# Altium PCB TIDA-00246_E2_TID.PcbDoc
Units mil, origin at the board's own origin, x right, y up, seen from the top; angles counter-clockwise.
Board outline 4000 x 2300 mil, 2 copper layers (Top Layer, Bottom Layer), stack 62 mil thick; 73 components, 44 nets, 230 pads, 54 vias.
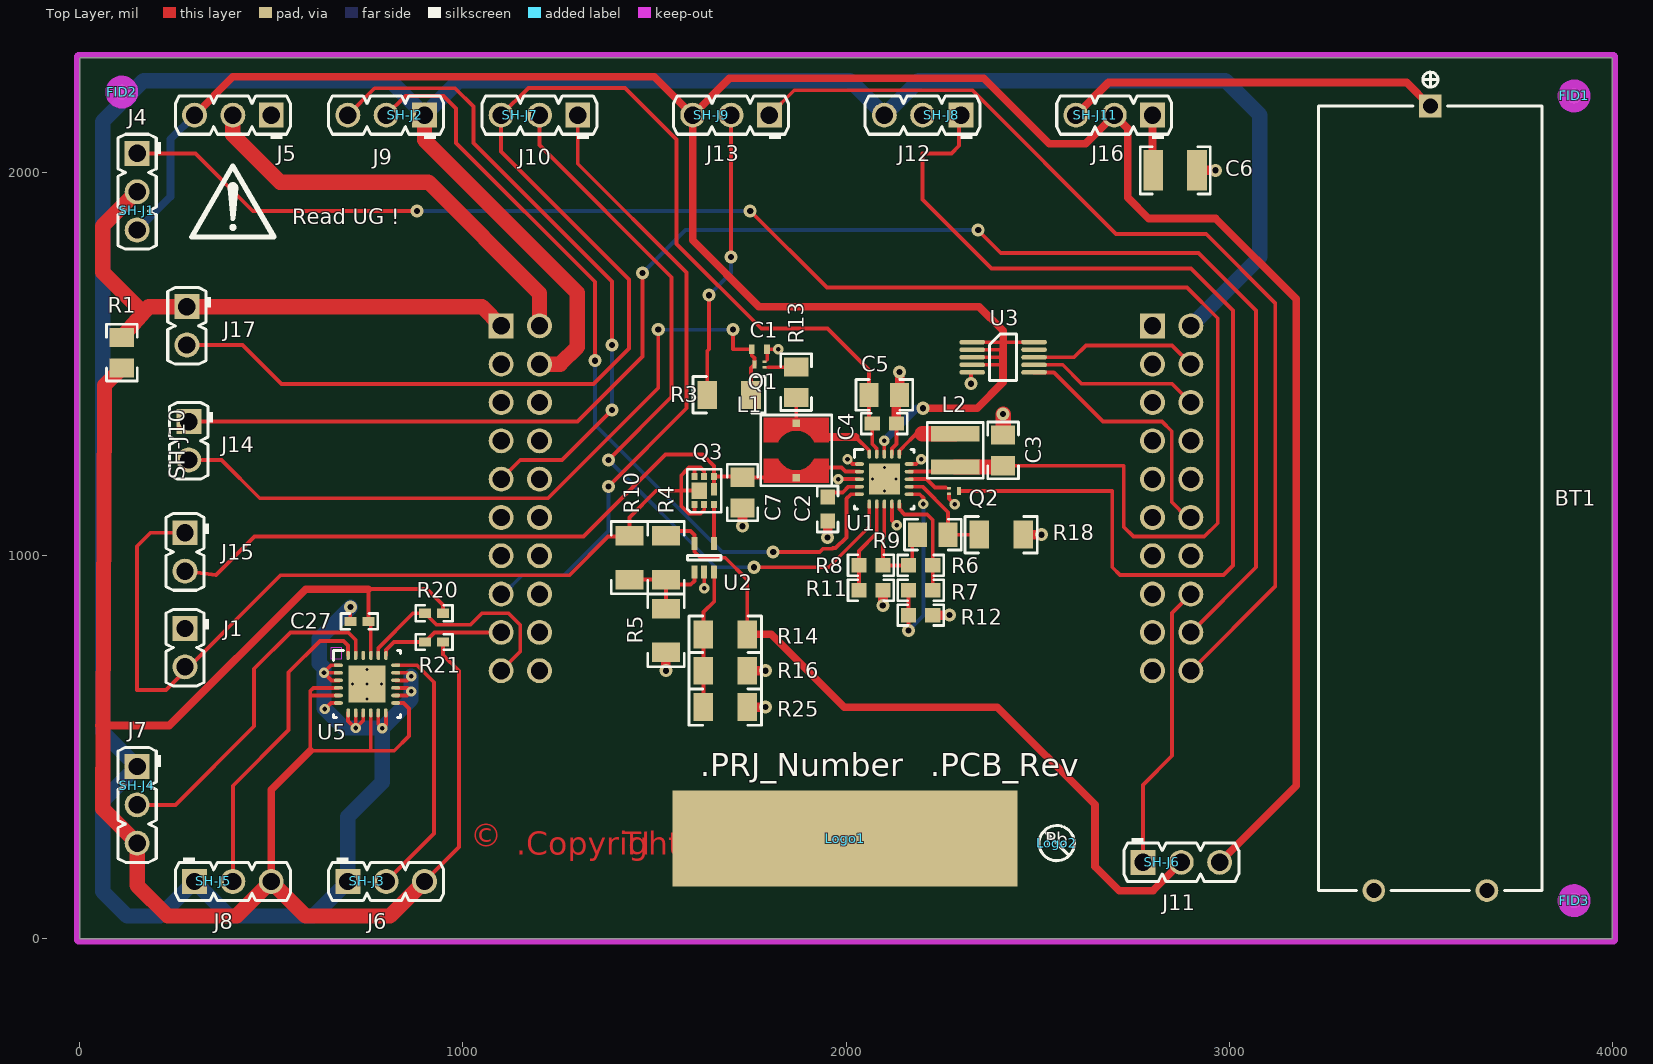
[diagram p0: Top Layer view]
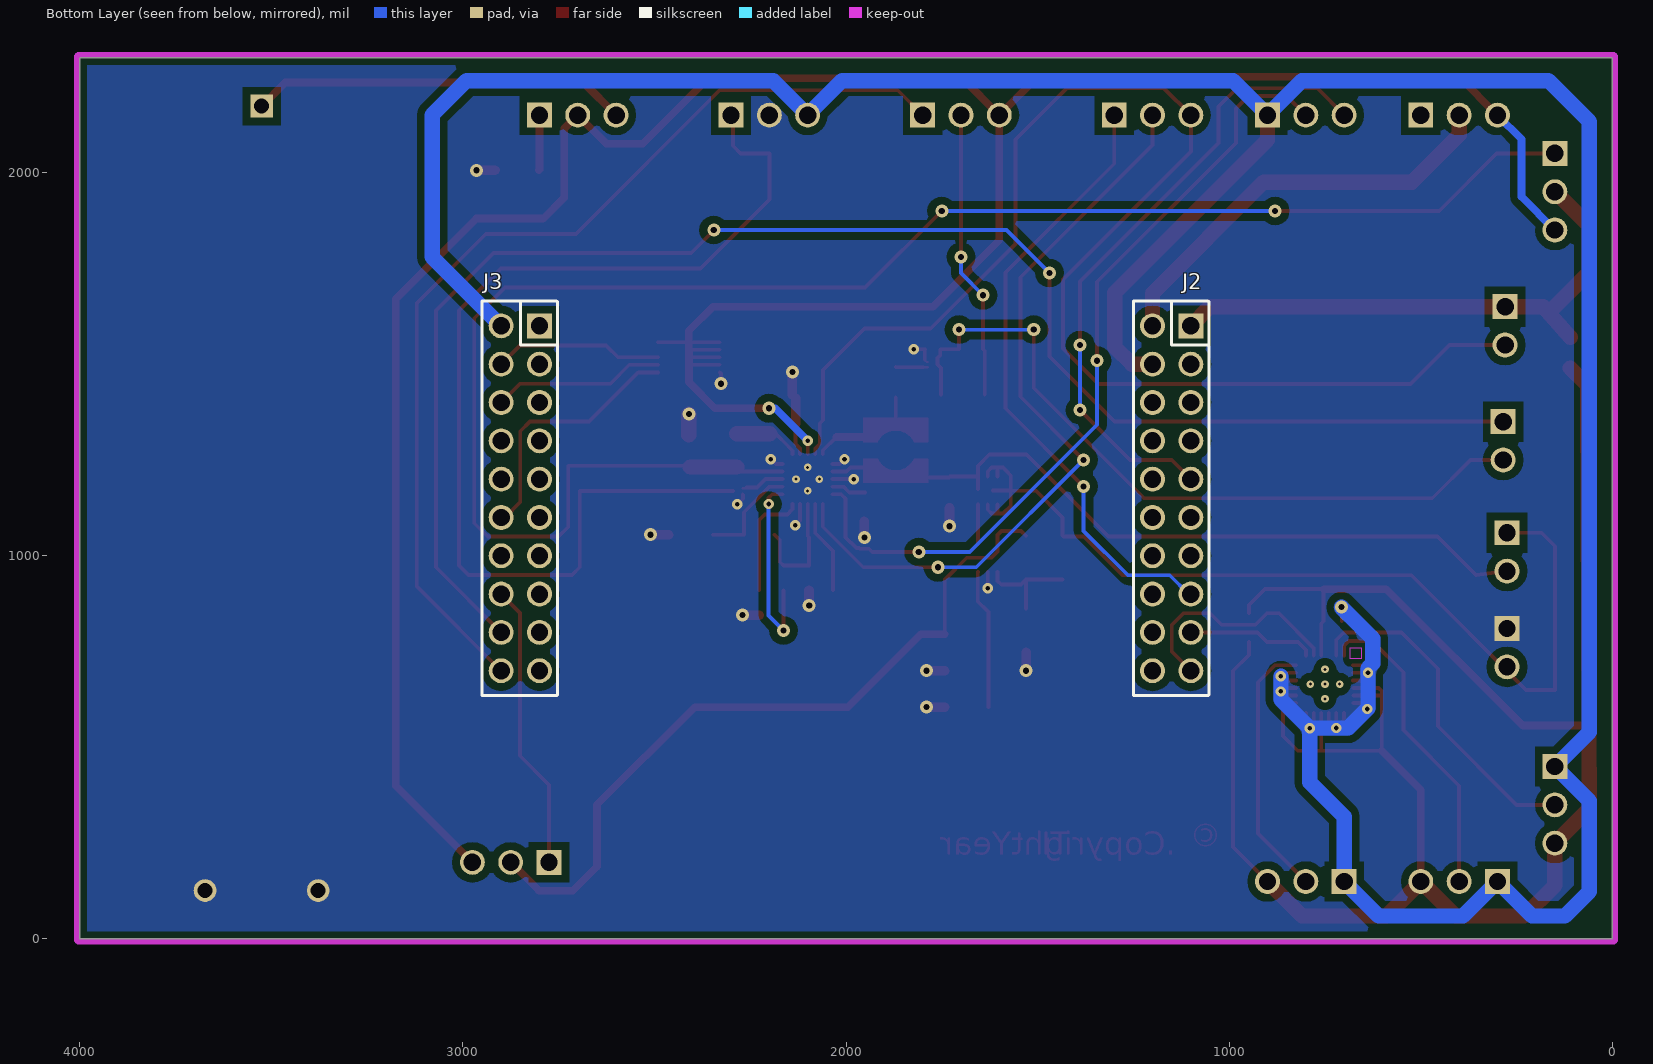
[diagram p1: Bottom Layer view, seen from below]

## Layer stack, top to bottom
Top Solder: solder mask 0.4, Solder Resist, Dk 3.5
Top Layer: signal copper 1.4
Dielectric1: core 59.2, FR-4, Dk 4.8
Bottom Layer: signal copper 1.4
Bottom Solder: solder mask 0.4, Solder Resist, Dk 3.5

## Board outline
0,0 4000,0 4000,2300 0,2300

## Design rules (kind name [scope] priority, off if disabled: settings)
AcuteAngle [All] p1: minimum=4.50000000000000E+0001 checktracksonly=FALSE
AssemblyTestPointUsage [All] p1: valid=2
Clearance Clearance_Keepouts [((IsTrack Or IsArc) And Not InPoly) And IsFree and IsKeepOut vs ((IsTrack Or IsArc) And Not InPoly) And IsFree and IsKeepOut] p1: gap=0
Clearance Clearance_BoardEdge_MountingHoles [OnCopper and InComponentClass('Mounting Holes') vs IsKeepOut] p2: gap=40
Clearance Clearance_BoardEdge_Poly [OnCopper and InPoly vs IsKeepOut] p3: gap=20
Clearance Clearance_BoardEdge [OnCopper and Not InComponentClass('Logo') and not InComponentClass('FiducialMark') and not InRegion(1000,500,4000,800) and Not IsKeepout vs IsKeepOut] p4: gap=75 except(10: Track-Fill SMDPad-Fill; 20: Via-Fill Poly-Poly THPad-Poly SMDPad-Poly Track-Poly Via-Poly Arc-Poly Fill-Poly; 40: Track-Track)
Clearance Clearance_Poly [InPolygon] p5: gap=20
Clearance [All] p6: gap=7.87
ComponentClearance ComponentClearance_MountingHoles_FiducialMarks [InComponentClass('Mounting Holes') vs InComponentClass('FiducialMark')] p1: gap=50 collisioncheckmode=3 verticalgap=10 showdistances=FALSE
ComponentClearance ComponentClearance_Shunt [InComponentClass('Header') vs InComponentClass('Shunt')] p2: gap=0 collisioncheckmode=3 verticalgap=0 showdistances=FALSE
ComponentClearance ComponentClearance_Logo [InComponentClass('Logo')] p3: gap=50 collisioncheckmode=3 verticalgap=10 showdistances=FALSE
ComponentClearance ComponentClearance_ScrewToNut [(HasFootprint('NY PMS 440 0025 PH')) vs (HasFootprint('Keystone_1902C'))] p4: gap=5 collisioncheckmode=3 verticalgap=10 showdistances=FALSE
ComponentClearance ComponentClearance_MountingHoles [InComponentClass('Mounting Holes')] p5: gap=250 collisioncheckmode=3 verticalgap=100000 showdistances=FALSE
ComponentClearance ComponentClearance_SmallPassives [HasFootprint('0201*') or HasFootprint('0402*') or HasFootprint('0508') or HasFootprint('0603*') or HasFootprint('0612') or HasFootprint('0805*') or HasFootprint('0815*') or HasFootprint('0830*') or HasFootprint('1206*') or HasFootprint('1210*') or HasFootprint('1808*') or HasFootprint('1812*') or HasFootprint('1825*') or HasFootprint('2010*') or HasFootprint('2220*') or HasFootprint('2225*') or HasFootprint('2512*') or HasFootprint('2728*') or HasFootprint('3518*') vs HasFootprint('0201*') or HasFootprint('0402*') or HasFootprint('0508') or HasFootprint('0603*') or HasFootprint('0612') or HasFootprint('0805*') or HasFootprint('0815*') or HasFootprint('0830*') or HasFootprint('1206*') or HasFootprint('1210*') or HasFootprint('1808*') or HasFootprint('1812*') or HasFootprint('1825*') or HasFootprint('2010*') or HasFootprint('2220*') or HasFootprint('2225*') or HasFootprint('2512*') or HasFootprint('2728*') or HasFootprint('3518*')] p6: gap=20 collisioncheckmode=3 verticalgap=10 showdistances=FALSE
ComponentClearance ComponentClearance_THtoSMT [IsThruComponent vs IsSMTComponent] p7: gap=40 collisioncheckmode=3 verticalgap=30 showdistances=FALSE
ComponentClearance ComponentClearance_THtoTH [IsThruComponent vs IsThruComponent] p8: gap=40 collisioncheckmode=3 verticalgap=30 showdistances=FALSE
ComponentClearance [All] p9: gap=0 collisioncheckmode=3 verticalgap=10 showdistances=FALSE
DiffPairsRouting [All] p1: maxlimit=100 minlimit=10 mostfreqgap=10 toplayer_minwidth=15 toplayer_maxwidth=15 toplayer_prefwidth=15 bottomlayer_minwidth=15 bottomlayer_maxwidth=15 bottomlayer_prefwidth=15 maxuncoupledlength=1000
FabricationTestPointUsage TestPointUsage [All] p1: valid=2 allowmultiple=FALSE
FabricationTestpoint Testpoint [All] p1: side=3 testpointundercomponent=TRUE minsize=40 maxsize=100 preferedsize=60 minholesize=0 maxholesize=40 preferedholesize=32 testpointgrid=1 allowsidetop=TRUE allowsidebottom=TRUE usegrid=TRUE gridtolerance=0.01
FanoutControl Fanout_LCC [IsLCC] p1: bgadir=Out bgaviamode=Centered fanoutstyle=Auto fanoutdirection=Alternating viagrid=1 // Fanout_LCC (Default Rule)
FanoutControl Fanout_BGA [IsBGA] p2: bgadir=Out bgaviamode=Centered fanoutstyle=Auto fanoutdirection=Alternating viagrid=1 // Fanout_BGA (Default Rule)
FanoutControl Fanout_Default [All] p4: bgadir=Out bgaviamode=Centered fanoutstyle=Auto fanoutdirection=Alternating viagrid=1 // Fanout_Default (Default Rule)
FanoutControl Fanout_Small [(CompPinCount < 5)] p5: bgadir=Out bgaviamode=Centered fanoutstyle=Auto fanoutdirection=OutThenIn viagrid=1 // Fanout_Small (Default Rule)
HoleSize [All] p1: absolutevalues=TRUE maxlimit=251 minlimit=7.87 maxpercent=80.000 minpercent=20.000
MinimumAnnularRing MinimumAnnularRing_ThermalPadVias [IsVia and InAnyComponent] p1: minimumring=5.91
MinimumAnnularRing [All] p2: minimumring=7.5
MinimumSolderMaskSliver MinimumSolderMaskSliver_Logo [InComponentClass('Logo') vs InComponentClass('Logo')] p1: minsoldermaskwidth=0.7
MinimumSolderMaskSliver [All] p2: minsoldermaskwidth=3.94
PlaneConnect [All] p1: planeconnectstyle=Direct reliefexpansion=10 reliefentries=4 reliefconductorwidth=10 reliefairgap=10
PolygonConnect PolygonConnect_Via [isVia] p1: connectstyle=Direct reliefconductorwidth=10 reliefentries=4 polygonreliefangle="90 Angle" airgapwidth=10
PolygonConnect [All] p2: connectstyle=Direct reliefconductorwidth=10 reliefentries=4 polygonreliefangle="90 Angle" airgapwidth=10
RoutingVias ThermalPadVias [IsVia and InAnyComponent] p1: holewidth=7.87 width=19.68 viastyle="Through Hole" minholewidth=7.87 minwidth=19.68 maxholewidth=12.99 maxwidth=23.62
RoutingVias [All] p2: holewidth=16 width=34 viastyle="Through Hole" minholewidth=7.87 minwidth=26 maxholewidth=40 maxwidth=65
SilkToSilkClearance SilkToSilkClearance_Pb-FreeLogo [(HasFootprint('Pb-Free_Overlay_Medium') OR HasFootprint('Pb-Free_Overlay_Small')) vs (HasFootprint('Pb-Free_Overlay_Medium') OR HasFootprint('Pb-Free_Overlay_Small'))] p1: silktosilkclearance=0
SilkToSilkClearance [All] p2: silktosilkclearance=5
SilkToSolderMaskClearance "Silk to Solder Mask Opening" [IsPad] p1: minsilkscreentomaskgap=1 clearancetoexposedcopper=TRUE
SolderMaskExpansion [All] p1: expansion=0
UnpouredPolygon [All] p1: allowunpoured=FALSE
Width [All] p1: maxlimit=100 minlimit=6 preferedwidth=10 checkconnectedcopper=TRUE
15 further rules are at their usual default settings.

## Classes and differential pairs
component class TIDA-00246_E2_BoosterPack: C27 J2 J3 J4 J5 J6 J7 J8 J9 J10 J11 J12 J13 J14 J17 R1 R20 R21 SH-J1 SH-J2 SH-J3 SH-J4 SH-J5 SH-J6 SH-J7 SH-J8 SH-J9 SH-J10 U5
component class Shunt: SH-J1 SH-J2 SH-J3 SH-J4 SH-J5 SH-J6 SH-J7 SH-J8 SH-J9 SH-J10 SH-J11
component class TIDA-00246_E2_Power: BT1 C1 C2 C3 C4 C5 C6 C7 J1-TEG J15 J16 L1 L2 Q1 Q2 Q3 R3 R4 R5 R6 R7 R8 R9 R10 R11 R12 R13 R14 R16 R18 R25 SH-J11 U1 U2 U3
component class AssemblyNote: ZZ1 ZZ2 ZZ3
component class FiducialMark: FID1 FID2 FID3
component class TIDA-00246_E2_TID_Hardware: FID1 FID2 FID3 Logo1 Logo2 "Read UG !" ZZ1 ZZ2 ZZ3
component class Logo: Logo1
component class Header: J1-TEG J4 J5 J6 J7 J8 J9 J10 J11 J12 J13 J14 J15 J16 J17

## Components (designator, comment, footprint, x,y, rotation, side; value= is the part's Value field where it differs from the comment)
BT1 "HLC-1550A/TP" Tadiran_HLC-1550A_TP 3525,1150 r270 top
C1 "C04ULR15D-6SN-X0T" 0402_70 1774,1539 r0 top
C2 "GRM188R71H103KA01D" 0603 1952,1122 r90 top
C3 "JMK212BJ226MG-T" 0805_HV 2410,1275 r90 top
C4 "06033D104KAT2A" 0603 2100,1345 r0 top
C5 "LMK212B7475KG-T" 0805_HV 2100,1420 r0 top
C6 "1210YD106KAT2A" 1210 2859,2006 r180 top
C7 "LMK212B7475KG-T" 0805_HV 1730,1165 r270 top
C27 "GRM155R71A104KA01D" 0402 730,829 r0 top
FID1 "Fiducial" Fiducial10-20 3900,2200 r0 top
FID2 "Fiducial" Fiducial10-20 110,2210 r0 top
FID3 "Fiducial" Fiducial10-20 3900,100 r0 top
J1 "61300211121" WURTH_61300211121 275,760 r270 top
J2 "SSW-110-23-F-D" CONN_SSW-110-23-F-D 1150,1150 r90 bottom locked
J3 "SSW-110-23-F-D" CONN_SSW-110-23-F-D 2850,1150 r90 bottom locked
J4 "61300311121" WURTH_61300311121 150,1950 r270 top
J5 "61300311121" WURTH_61300311121 400,2150 r180 top
J6 "61300311121" WURTH_61300311121 800,150 r0 top
J7 "61300311121" WURTH_61300311121 150,350 r270 top
J8 "61300311121" WURTH_61300311121 400,150 r0 top
J9 "61300311121" WURTH_61300311121 800,2150 r180 top
J10 "61300311121" WURTH_61300311121 1200,2150 r180 top
J11 "61300311121" WURTH_61300311121 2875,200 r0 top
J12 "61300311121" WURTH_61300311121 2200,2150 r180 top
J13 "61300311121" WURTH_61300311121 1700,2150 r180 top
J14 "61300211121" WURTH_61300211121 285,1300 r270 top
J15 "61300211121" WURTH_61300211121 275,1010 r270 top
J16 "61300311121" WURTH_61300311121 2700,2150 r180 top
J17 "61300211121" WURTH_61300211121 280,1600 r270 top
L1 "744031220" WE-TPC-S 1870,1275 r90 top
L2 "744029100" WE-TPC_2813 2285,1275 r90 top
Logo1 "Texas Instruments" TI_Stacked_SolderMask_Small 1997.8,262 r0 top
Logo2 "Pb-Free Symbol" Pb-Free_Overlay_Small 2550,250 r0 top
Q1 "CSD17483F4T" YJC0003A#1 1774,1499 r90 top
Q2 "CSD17483F4T" YJC0003A#2 2282,1169 r270 top
Q3 "CSD13202Q2" TRANS_NexFET_Q2 1630,1170 r90 top
R1 "CRCW08050000Z0EA" 0805_HV 110,1530 r90 top
R3 "CRCW120610M0FKEA" 1206 1695,1420 r180 top
R4 "CRCW12066M81FKEA" 1206 1530,995 r90 top
R5 "CRCW12064M53FKEA" 1206 1530,805 r90 top
R6 "CRCW0603510KJNEA" 0603 2195,975 r180 top
R7 "CRCW06036M49FKEA" 0603 2195,910 r0 top
R8 "CRCW06036M49FKEA" 0603 2065,975 r0 top
R9 "CRCW08055M23FKEA" 0805_HV 2226.5,1055 r180 top
R10 "CRCW120610M0FKEA" 1206 1435,995 r90 top
R11 "CRCW06036M34FKEA" 0603 2065,910 r0 top
R12 "CRCW06036M04FKEA" 0603 2195,845 r0 top
R13 "CRCW08050000Z0EA" 0805_HV 1870,1453 r90 top
R14 "CRCW12066M81FKEA" 1206 1685,795 r0 top
R16 "CRCW12064M53FKEA" 1206 1685,700 r180 top
R18 "CRCW12067M87FKEA" 1206 2405,1055 r180 top
R20 "CRCW04021K50JNED" 0402 925,850 r0 top
R21 "CRCW04021K50JNED" 0402 925,775 r0 top
R25 "CRCW120610M0FKEA" 1206 1685,605 r180 top
"Read UG !" "CAUTION.  READ USER GUIDE BEFORE USE" IEC_Caution_Small 400,1925 r0 top
SH-J1 "969102-0000-DA" SNT-100-BK-G 150,1900 r90 top
SH-J2 "969102-0000-DA" SNT-100-BK-G 850,2150 r180 top
SH-J3 "969102-0000-DA" SNT-100-BK-G 750,150 r180 top
SH-J4 "969102-0000-DA" SNT-100-BK-G 150,400 r90 top
SH-J5 "969102-0000-DA" SNT-100-BK-G 350,150 r180 top
SH-J6 "969102-0000-DA" SNT-100-BK-G 2825,200 r180 top
SH-J7 "969102-0000-DA" SNT-100-BK-G 1150,2150 r180 top
SH-J8 "969102-0000-DA" SNT-100-BK-G 2250,2150 r0 top
SH-J9 "969102-0000-DA" SNT-100-BK-G 1650,2150 r0 top
SH-J10 "969102-0000-DA" SNT-100-BK-G 150,1300 r270 top
SH-J11 "969102-0000-DA" SNT-100-BK-G 2650,2150 r180 top
U1 "BQ25570RGRR" RGR0020A 2100,1200 r0 top
U2 "TLV3691IDCK" DCK0005A_N 1630,995 r90 top
U3 "TPL5100DGS" DGS0010A_N 2410,1518 r0 top
U5 "TCA9535RTWR" RTW0024B 750,665 r0 top
ZZ1 "This Assembly Note will show in the PcbDoc and associated outputs" AssemblyNote 185,3829.11 r0 top
ZZ2 "This Assembly Note will show in the PcbDoc and associated outputs" AssemblyNote 185,3740.56 r0 top
ZZ3 "This Assembly Note will show in the PcbDoc and associated outputs" AssemblyNote 185,3652 r0 top

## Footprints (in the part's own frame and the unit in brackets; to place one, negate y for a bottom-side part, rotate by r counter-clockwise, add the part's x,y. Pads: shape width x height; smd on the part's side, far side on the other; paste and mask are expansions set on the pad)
0402 [mm] "0402 from SM-752 data"
  rect 0.8x0.6 smd: 1(-0.6,0) 2(0.6,0)
  silkscreen extent -1.22,-0.52 1.22,0.52, body extent -0.55,-0.3 0.55,0.3, height 0.6
0402_70 [mil] "SMD, 2-Leads, Body 1.2x0.7mm, Height 0.7mm"
  rect 15x24 smd: 1(-20,0) 2(20,0)
  body extent -24,-14 24,14, height 28
0603 [mm] "0603 from SM-752 data"
  rect 1x0.95 smd: 1(-0.8,0) 2(0.8,0)
  silkscreen extent -1.52,-0.69 1.52,0.69, body extent -0.87,-0.47 0.87,0.47, height 0.85
0805_HV [mil] "0805 with 30mil clearance between pads"
  rect 50x63 smd: 1(-40,0) 2(40,0)
  silkscreen extent -74,-40 74,40, body extent -43,-29 43,29, height 43
1206 [mm] "1206 from SM-752 data"
  rect 1.3x1.85 smd: 1(-1.45,0) 2(1.45,0)
  silkscreen extent -2.4,-1.21 2.4,1.21, body extent -1.7,-0.9 1.7,0.9, height 1.35
1210 [mm] "1210 from SM-752 data"
  rect 1.3x2.7 smd: 1(-1.45,0) 2(1.45,0)
  silkscreen extent -2.32,-1.57 2.32,1.57, body extent -1.7,-1.35 1.7,1.35, height 1.35
AssemblyNote [mil] "Assembly Note"
CONN_SSW-110-23-F-D [mm] "SAMTEC"
  rect 1.65x1.65 hole 1.15: 1(11.43,-1.27)
  round 1.65 hole 1.15: 2(11.43,1.27) 3(8.89,-1.27) 4(8.89,1.27) 5(6.35,-1.27) 6(6.35,1.27) 7(3.81,-1.27) 8(3.81,1.27) 9(1.27,-1.27) 10(1.27,1.27) 11(-1.27,-1.27) 12(-1.27,1.27) 13(-3.81,-1.27) 14(-3.81,1.27) 15(-6.35,-1.27) 16(-6.35,1.27) 17(-8.89,-1.27) 18(-8.89,1.27) 19(-11.43,-1.27) 20(-11.43,1.27)
  silkscreen extent -13.08,-2.46 13.08,2.54, body extent -13,-2.51 13,2.54, height 8.59
DCK0005A_N [mm] "SOT353, 5-Leads, Body 2x1.3mm, Pitch 0.65mm, Lead Span 2.1mm, IPC Medium Density"
  rect 0.85x0.4 smd: 1(-0.95,0.65) 2(-0.95,0) 3(-0.95,-0.65) 4(0.95,-0.65) 5(0.95,0.65)
  silkscreen extent -0.15,-1.1 0.15,1.1, body extent -1.14,-1 1.14,1, height 0.94
DGS0010A_N [mm] "TSSOP, 10-Leads, Body 3x3mm, Pitch 0.5mm, IPC Medium Density"
  oval 1.7x0.3 smd: 1(-2.05,1) 2(-2.05,0.5) 3(-2.05,0) 4(-2.05,-0.5) 5(-2.05,-1) 6(2.05,-1) 7(2.05,-0.5) 8(2.05,0) 9(2.05,0.5) 10(2.05,1)
  silkscreen extent -0.9,-1.55 0.9,1.55, body extent -2.45,-1.5 2.45,1.5, height 0.94
Fiducial10-20 [mm]
  round 1 smd mask+0.5: 1(0,0)
  Top Layer keep-out circle w1.178: c0,0 r0.5
IEC_Caution_Small [mil]
  silkscreen extent -107,-93 107,92
Pb-Free_Overlay_Small [mil]
  silkscreen extent -46,-46 46,46
RGR0020A [mm] "QFN, 20-Leads, Body 3.5x3.5mm, Pitch 0.5mm, Thermal Pad 2.05x2.05mm, TI Recommended"
  oval 0.6x0.24 smd: 1(-1.65,1) 2(-1.65,0.5) 3(-1.65,0) 4(-1.65,-0.5) 5(-1.65,-1) 11(1.65,-1) 12(1.65,-0.5) 13(1.65,0) 14(1.65,0.5) 15(1.65,1)
  oval 0.24x0.6 smd: 6(-1,-1.65) 7(-0.5,-1.65) 8(0,-1.65) 9(0.5,-1.65) 10(1,-1.65) 16(1,1.65) 17(0.5,1.65) 18(0,1.65) 19(-0.5,1.65) 20(-1,1.65)
  rect 2.05x2.05 smd paste-1.025: 21(0,0)
  silkscreen extent -1.97,-1.97 1.97,1.97, body extent -1.83,-1.83 1.83,1.83, height 1.01
RTW0024B [mm] "QFN, 24-Leads, Body 4x4mm, Pitch 0.5mm, Thermal Pad 2.45x2.45mm, TI Recommended"
  oval 0.6x0.24 smd: 1(-1.9,1.25) 2(-1.9,0.75) 3(-1.9,0.25) 4(-1.9,-0.25) 5(-1.9,-0.75) 6(-1.9,-1.25) 13(1.9,-1.25) 14(1.9,-0.75) 15(1.9,-0.25) 16(1.9,0.25) 17(1.9,0.75) 18(1.9,1.25)
  oval 0.24x0.6 smd: 7(-1.25,-1.9) 8(-0.75,-1.9) 9(-0.25,-1.9) 10(0.25,-1.9) 11(0.75,-1.9) 12(1.25,-1.9) 19(1.25,1.9) 20(0.75,1.9) 21(0.25,1.9) 22(-0.25,1.9) 23(-0.75,1.9) 24(-1.25,1.9)
  rect 2.45x2.45 smd paste-1.225: 25(0,0)
  Keep-Out Layer region: -2.4,1.68 -1.68,1.68 -1.68,2.4 -2.4,2.4
  silkscreen extent -2.22,-2.22 2.22,2.22, body extent -2.07,-2.07 2.07,2.07, height 0.81
SNT-100-BK-G [mil] "Samtec STEP model"
  round 1 on Mech3: 0(0,0)
  body extent -100,-50 100,50, height 344
Tadiran_HLC-1550A_TP [mm] "SMD, 3-Leads, Dia 14.8mm, Length 52mm"
  rect 1.5x1.5 hole 1: 1(-26,0)
  round 1.5 hole 1: 2(26,-3.75) 2(26,3.75)
  silkscreen extent -28.25,-7.4 26,7.4, body extent -26.1,-7.37 26.1,7.4, height 14.74
TI_Stacked_SolderMask_Small [mil]
  rect 900x250 smd paste-125 mask-125: 0(0,0)
TRANS_NexFET_Q2 [mm] "TI recommended land pattern M0167-01"
  rect 0.46x0.4 smd mask+0.051: 1(-0.93,0.65) 2(-0.93,0) 3(-0.93,-0.65) 4(0.93,-0.65) 5(0.93,0) 6(0.93,0.65)
  rect 0.85x0.4 smd paste-0.025 mask+0.051: 7(0.095,-0.65)
  rect 1.1x1.05 smd paste-0.05 mask+0.102: 8(0,0.325)
  silkscreen extent -1.43,-1.12 1.43,1.12, body extent -1,-1 1,1, height 0.85
WE-TPC-S [mm] "Wurth Elektronik recommended land pattern"
  rect 0.5x0.5 smd: 1(-1.8,0) 2(1.8,0)
  Top Layer region: -0.55,1.185 -0.658,1.14 -0.931,0.931 -1.14,0.658 -1.271,0.341 -1.316,0 -1.271,-0.341 -1.14,-0.658 -0.931,-0.931 -0.658,-1.14 -0.55,-1.185 -0.55,-2.15 -2.15,-2.15 -2.15,2.15 -0.55,2.15
  Top Layer region: 2.15,-2.15 0.55,-2.15 0.55,-1.185 0.658,-1.14 0.931,-0.931 1.14,-0.658 1.271,-0.341 1.316,0 1.271,0.341 1.14,0.658 0.931,0.931 0.658,1.14 0.55,1.185 0.55,2.15 2.15,2.15
  silkscreen extent -2.35,-2.35 2.35,2.35, body extent -2.06,-2.06 2.06,2.06, height 1.8
WE-TPC_2813 [mm] "Wurth Elektronik recommended land pattern"
  rect 1x3.2 smd: 1(-1.1,0) 2(1.1,0)
  silkscreen extent -1.85,-1.85 1.85,1.85, body extent -1.5,-1.5 1.5,1.5, height 1.5
WURTH_61300211121 [mm] "Header, 2.54mm, 2x1, TH"
  rect 1.65x1.65 hole 1.15: 1(-1.27,0)
  round 1.65 hole 1.15: 2(1.27,0)
  silkscreen extent -2.54,-1.27 2.54,1.6, body extent -2.54,-1.27 2.54,1.27, height 8.54
WURTH_61300311121 [mm] "Header, 2.54mm, 3x1, TH"
  rect 1.65x1.65 hole 1.15: 1(-2.54,0)
  round 1.65 hole 1.15: 2(0,0) 3(2.54,0)
  silkscreen extent -3.81,-1.27 3.81,1.6, body extent -3.81,-1.27 3.81,1.27, height 8.54
YJC0003A#1 [mm] "TI"
  rect 0.16x0.26 smd: 1(-0.175,-0.325) 2(0.175,-0.325)
  rect 0.51x0.26 smd: 3(0,0.325)
  body extent -0.32,-0.52 0.32,0.52, height 0.35
YJC0003A#2 [mm] "TI"
  rect 0.16x0.26 smd: 1(-0.175,-0.325)
  rect 0.16x0.26 smd mask+0.05: 2(0.175,-0.325)
  rect 0.51x0.26 smd: 3(0,0.325)
  body extent -0.32,-0.52 0.32,0.52, height 0.35

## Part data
BT1: "Battery, 3.95 V, Axial, TH"
C1: "CAP, CERM, 0.15 pF, 200 V, +/- %, X7R, 0402"
C2: "CAP, CERM, 0.01uF, 50V, +/-10%, X7R, 0603"
C3: "CAP, CERM, 22uF, 6.3V, +/-20%, X5R, 0805"
C4: "CAP, CERM, 0.1uF, 25V, +/-10%, X5R, 0603"
C5 C7: "CAP, CERM, 4.7uF, 10V, +/-10%, X7R, 0805"
C6: "CAP, CERM, 10 µF, 16 V, +/- 10%, X5R, 1210"
C27: "CAP, CERM, 0.1uF, 10V, +/-10%, X7R, 0402"
FID1 FID2 FID3: "Fiducial mark.  There is nothing to buy or mount."
J1 J14 J15 J17: "Header, 2.54 mm, 2x1, Gold, TH"
J2 J3: "Connector, Receptacle, 100mil, 10x2, Gold plated, TH"
J4 J5 J6 J7 J8 J9 J10 J11 J12 J13 J16: "Header, 2.54 mm, 3x1, Gold, TH"
L1: "Inductor, Shielded Drum Core, Ferrite, 22 µH, 0.36 A, 0.41 ohm, SMD"
L2: "Inductor, Shielded Drum Core, Ferrite, 10 µH, 0.5 A, 0.39 ohm, SMD"
Logo1: library part TI_Logo, "Texas Instrument Corporate Signature"
Logo2: library part Pb-Free
Q1 Q2: "MOSFET, N/P-CH, 30 V, 1.5 A, 1.0x0.35x0.6mm"
Q3: "MOSFET, N-CH, 12 V, 14.4 A, SON 2x2mm"
R1 R13: "RES, 0, 5%, 0.125 W, 0805"
R3 R10 R25: "RES, 10.0 M, 1%, 0.25 W, 1206"
R4 R14: "RES, 6.81 M, 1%, 0.25 W, 1206"
R5 R16: "RES, 4.53 M, 1%, 0.25 W, 1206"
R6: "RES, 510k ohm, 5%, 0.1W, 0603"
R7 R8: "RES, 6.49Meg ohm, 1%, 0.1W, 0603"
R9: "RES, 5.23 M, 1%, 0.125 W, 0805"
R11: "RES, 6.34Meg ohm, 1%, 0.1W, 0603"
R12: "RES, 6.04Meg ohm, 1%, 0.1W, 0603"
R18: "RES, 7.87 M, 1%, 0.25 W, 1206"
R20 R21: "RES, 1.5k ohm, 5%, 0.063W, 0402"
"Read UG !": library part IEC_Caution, "IEC 61010-1 Caution Warning"
SH-J1 SH-J2 SH-J3 SH-J4 SH-J5 SH-J6 SH-J7 SH-J8 SH-J9 SH-J10 SH-J11: "Shunt, 100mil, Gold plated, Black"
U1: "Ultra Low Power Harvester Power Management IC with Boost Charger, and Nano-Powered Buck Converter, RGR0020A"
U2: "0.9-V to 6.5-V, Nanopower Comparator, DCK0005A"
U3: "Nano Power Programmable Timer, DGS0010A"
U5: "Remote 16-Bit I2C and SMBus, Low-Power I/O Expander with Interrupt Output and Config Register, 1.65 to 5.5 V, -40 to 85 degC, 24-pin QFN (RTW), Green (RoHS & no Sb/Br)"
ZZ1 ZZ2 ZZ3: library part AssemblyNote

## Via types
v1: diameter 34, hole 16, Top Layer to Bottom Layer, tented both sides, 30 vias
v2: diameter 27, hole 12, Top Layer to Bottom Layer, tented both sides, 15 vias
v3: diameter 19.68, hole 7.87, Top Layer to Bottom Layer, 9 vias

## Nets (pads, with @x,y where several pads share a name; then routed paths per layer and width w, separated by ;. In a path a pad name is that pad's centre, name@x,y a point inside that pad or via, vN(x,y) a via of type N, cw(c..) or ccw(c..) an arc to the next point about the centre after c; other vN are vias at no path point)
3V3: J2.1 J4.2 J17.1 R1.2 | length 1451.6
  Top Layer w40: R1.2 180,1650 1050,1650 J2.1 ; 150,1650 60,1740 60,1860 J4.2 ; J17.1@250,1650 J17.1
5V0: J2.2 J5.2 | length 1108.1
  Top Layer w40: J5.2 400,2098 523,1975 910,1975 1200,1685 J2.2
+3V3_BP: C27.2 J6.3 J7.3 J8.3 R1.1 R20.2 R21.2 U5.4 U5.5 U5.10 U5.13 U5.21 | length 5416.4
  Top Layer w10: U5.5 604.47,635.47 602,633 ; U5.4 610.16,655.16 602,647 602,633 ; 759.84,491.16 U5.10 ; U5.21 759.84,822.78 C27.2 753.62,913 907,913 948.62,871.38 R20.2 ; U5.13 845.21,615.79 860,601 860,530 821,491 602,491 602,633 ; J6.3 990,240 990,700 948.62,741.38 R21.2
  Top Layer w20: 50,557 234,557 590,913 753.62,913 ; J8.3 500,389 602,491
  Top Layer w40: R1.1 65,1445 65,1410 61.01,557 60,340 J7.3 150,140 230,60 410,60 J8.3 590,60 810,60 J6.3
AFE_3.6V: J11.2 R4.2 R14.2 U2.5 | length 1973.8
  Top Layer w10: R4.2 1542.91,1065 1594,1065 1604.41,1054.59 U2.5 1604.41,1010.59 1620,995 1685,995 1742.09,937.91 R14.2
  Top Layer w20: R14.2 1805,795 1995,605 2395,605 2650,350 2650,189 2713,126 2801,126 J11.2
BP_BUCKEN/: J2.15 J10.1 | length 1640.8
  Top Layer w10: J2.15 J2.15@1105.28,900 ; J10.1 1300,2023 1584,1739 1584,1385 v1(1380,1181)
  Bottom Layer w10: J2.15 1106,900 1155,949 1264,949 1380,1065 v1(1380,1181)
BP_CHEN/: J2.9 J9.3 | length 1682
  Top Layer w10: J9.3 770,2220 980,2220 1028,2172 1028,2077 1389,1716 v1(1389,1550) ; J2.9 1150,1250 1259,1250 v1(1389,1380)
  Bottom Layer w10: v1(1389,1380) v1(1389,1550)
BP_EN_PULSESTRECHER: J3.20 J13.1 | length 2627.9
  Top Layer w10: J13.1 1865,2215 2330,2215 2705,1840 2940,1840 3120,1660 3120,920 J3.20
BP_FE_ENABLE: J3.16 J11.1 | length 751.8
  Top Layer w10: J11.1 2775,402 2851,478 2851,851 J3.16
BP_HARVESTER_CHARGING: J3.18 J14.1 | length 4117.8
  Top Layer w10: J14.1 1299,1350 1469,1520 v1(1469,1738) ; v1(2345,1850) 2345,1849 2404,1790 2920,1790 3070,1640 3070,970 J3.18
  Bottom Layer w10: v1(1469,1738) 1581,1850 v1(2345,1850)
CHARGING: C1.1 J14.2 Q1.3 R3.1 | length 1957.5
  Top Layer w10: J14.2 370,1250 470,1150 1222,1150 1510,1438 v1(1510,1590) ; v1@1705.5,1589.5 1705.5,1539 C1.1 1754,1523 1761.2,1515.8 Q1.3 1752.09,1489.88 R3.1
  Bottom Layer w10: v1(1510,1590) v1(1705,1590)
CHEN/: J9.2 U1.5 | length 2141.4
  Top Layer w10: J9.2 850,2200 950,2200 982.5,2167.5 982.5,2077.5 1345,1715 v1(1345,1509) ; v1(1810,1010) 1931.5,1010 1939.63,1018.13 1964.37,1018.13 1966.25,1020 1973,1020 2001,1048 2001,1149 2012.63,1160.63 U1.5
  Bottom Layer w10: v1(1345,1509) 1345,1342 1677,1010 v1(1810,1010)
DONE: J3.12 U3.6 | length 674.5
  Top Layer w10: U3.6 2542.37,1478.63 2671,1350 2825,1350 2850,1325 2850,1140 2890,1100 J3.12
GND: C27.1 J2.4 J3.2 J6.1 J7.1 J8.1 J9.1 J12.3 U5.1 U5.2 U5.3 U5.6 U5.7 U5.8 U5.9 U5.11 U5.12 U5.14 U5.15 U5.16 U5.17 | length 9322.7
  Top Layer w10: v2(640,600) 655.79,615.79 U5.6 ; U5.3@677.39,674.84 U5.3 657.35,674.84 v2(637.67,694.53) ; U5.2@677.39,694.53 U5.2 v2(637.67,694.53) ; U5.1@677.39,714.21 U5.1 656.41,714.21 637.2,695 v2(637.67,694.53) ; U5.7 700.79,569.21 720,550 v2(720.47,550.47) ; C27.1 706.38,863.38 707,864 v1(707,866) ; U5.8 v2(720.47,550.47) ; U5.9 740.16,570.16 v2(720.47,550.47) ; U5.11 779.53,560.47 v2(790,550) 799.21,559.21 U5.12 ; U5.14 854.53,635.47 v2(865,645.94) 855.79,655.16 U5.15 ; U5.16 854.53,674.84 v2(865,685.31) 855.79,694.53 U5.17
  Top Layer w40: J9.1 900,2085 1299,1686 1299,1545 1254,1500 J2.4
  Bottom Layer w40: v1(707,866) 707,865.56 625.51,784.07 625.51,718.72 637.67,706.56 v2(637.67,694.53) 637.67,602.33 v2(640,600) 689.53,550.47 v2(720.47,550.47) 789.53,550.47 v2(790,550) ; v2(865,685.31) v2(865,645.94) 865,625 v2(790,550) ; J3.2 3080,1780 3080,2150 2990,2240 2190,2240 J12.3 2010,2240 990,2240 J9.1 810,2240 167,2240 60,2133 60,540 J7.1 60,360 60,124 124,60 210,60 J8.1 390,60 610,60 J6.1 700,319 790,409 v2(790,550)
GND_EH: BT1.2 C1.2 C2.1 C3.2 C4.2 C5.2 C6.1 C7.2 J1.1 J12.2 Q1.2 Q2.2 R5.1 R11.2 R12.2 R16.1 R18.1 R25.1 U1.1 U1.3 U1.9 U1.15 U1.17 U1.21 U2.2 U3.5 | length 1074.6
  Top Layer w6: Q1.2 1788.76,1505.89 1794.47,1511.6 1794.47,1522.07 ; 2269.2,1154.2 Q2.2 ; v1@2410,1369 v1(2410,1370)
  Top Layer w10: v2(1630,915) U2.2 ; 1794.47,1511.6 1794.47,1538.53 C1.2 v2@1820,1539 ; v2(1980,1200) U1.3 ; v2(2004,1252) 2016.63,1239.37 U1.1 ; U1.9 2119.68,1092.32 v2(2132,1080) ; U1.17 2119.68,1279.68 2131.5,1291.5 C4.2 ; C5.2@2131.5,1411.5 C5.2 ; U1.15 2183.37,1239.37 v2(2196,1252) ; Q2.2@2269.2,1159 2269.2,1148.8 v2(2284,1134) v2@2292,1134 ; v1(2326,1449) 2326,1475.34 U3.5
  Top Layer w25: v1(1530,700) R5.1 ; v1(1730,1077.09) C7.2 ; R25.1 v1(1790,605) ; R16.1 v1(1790,700) ; v1(1952,1048) C2.1 ; v1(2096,870) 2096.5,870.5 R11.2 ; C4.2 C5.2@2131.5,1411.5 ; C5.2 v1(2140,1480) ; R12.2 v1(2270,845) ; R18.1 v1(2510,1055) ; C6.1 v1(2964,2006)
  Top Layer w40: C3.2 v1@2410,1369
  other v2: 1823,1539
  other v3: 2100,1169.49 2069.49,1200 2130.51,1200 2100,1230.51
GND_VBATT: J12.1 Q2.3 | length 2833.3
  Top Layer w10: Q2.3 2695,1169 2695,970 2715,950 2985,950 3010,975 3010,1640 2900,1750 2380,1750 2200,1930 2200,2050 2275,2050 2295,2070 2295,2145 J12.1
I2C_SCL: J2.17 R21.1 U5.19 | length 334
  Top Layer w10: U5.19 799.21,753.93 820.28,775 R21.1 926.38,800 J2.17
I2C_SDA: J2.19 R20.1 U5.20 | length 605.1
  Top Layer w10: U5.20 779.53,759.53 870,850 R20.1 931.38,820 1020,820 1050,850 1119,850 1150,819 1150,750 J2.19
NetBT1_1: BT1.1 J16.3 | length 985.6
  Top Layer w20: J16.3 2685,2235 3463.62,2235 BT1.1
NetC2_2: C2.2 U1.4 | length 91.2
  Top Layer w10: C2.2@1950,1165.5 1991.5,1165.5 2006.32,1180.32 U1.4
NetC6_2: C6.2 J16.1 | length 144.8
  Top Layer w20: J16.1 2800,2007.91 C6.2
NetJ6_2: J6.2 U5.18 | length 690.3
  Top Layer w10: J6.2 925,275 925,670 880.79,714.21 U5.18
NetJ7_2: J7.2 U5.23 | length 893.5
  Top Layer w10: J7.2 250,350 455,555 455,705 550,800 701,800 720.47,780.53 U5.23
NetJ8_2: J8.2 U5.24 | length 827.1
  Top Layer w10: J8.2 400,400 545,545 545,696 627,778 689,778 700.79,766.21 U5.24
NetL1_2: L1.2 R13.1 U1.20 | length 296.8
  Top Layer w10: R13.1 L1.2 1909.13,1345.87 1945,1310 ; 2025,1310 2060.63,1274.37 U1.20
  Top Layer w20: 1945,1310 2025,1310
NetL2_2: L2.2 U1.16 | length 173.2
  Top Layer w10: U1.16 2139.37,1274.09 2149.37,1284.09 2149.37,1284.37 2183,1318 2199,1318
  Top Layer w40: 2199,1318 2199.31,1318.31 L2.2
NetQ1_1: Q1.1 R13.2 | length 83.6
  Top Layer w6: Q1.1 1797,1492.11
  Top Layer w10: 1797,1492.11 1869.11,1492.11 R13.2
NetQ3_3: Q3.3 U2.4 | length 101
  Top Layer w10: U2.4 Q3.3
NetR6_1: R6.1 R7.2 U1.10 | length 295.7
  Top Layer w10: U1.10 2139.37,1121.63 2153,1108 2212,1108 2226.5,1093.5 R6.1 R7.2
NetR8_1: R8.1 R11.1 U1.7 | length 244.4
  Top Layer w10: R11.1 R8.1 2033.5,1012.5 2080.31,1059.31 U1.7
NetR9_1: R9.1 R18.2 U1.12 | length 269.1
  Top Layer w10: U1.12 2199.68,1180.32 2266.5,1113.5 R9.1 R18.2
OK_PROG: R7.1 R12.1 U1.11 | length 509.1
  Top Layer w10: v1(2163.01,805) 2163.01,844.5 R12.1 R7.1 ; U1.11 2192.37,1160.63 2202,1151 v2(2202,1135)
  Top Layer w25: v1(2163.01,805) v1@2163.5,805.5
  Bottom Layer w10: v1(2163.01,805) 2202,843.99 v2(2202,1135)
TCAL: J3.6 U3.7 | length 450
  Top Layer w10: U3.7 2565.68,1498.32 2615,1449 2851,1449 J3.6
TEG\_VP: J1.2 J15.1 Q3.1 Q3.2 Q3.5 Q3.6 Q3.8 R10.2 | length 2524
  Top Layer w10: J15.1 185,1060 150,1025 150,650 225,650 524,949 1278,949 1379,1050 1432.91,1050 R10.2 1435,1100 1504.86,1169.86 1570,1169.86 ; Q3.1 1604.41,1110.59 1605,1110 ; Q3.6 1604.41,1229.41 1605,1230 ; Q3.8 1570.14,1170 1570,1169.86 ; Q3.2 1630,1120 1620,1110 1605,1110 ; Q3.5 1630,1220 1620,1230 1605,1230 ; 1570,1169.86 1570,1209.72 1582.87,1222.6 1582.87,1222.87 1590,1230 1605,1230 ; 1570,1169.86 1570,1130 1590,1110 1605,1110
TEG\_VP_PROT: C7.1 J15.2 L1.1 Q3.4 Q3.7 U1.2 | length 1979.7
  Top Layer w10: J15.2 356,950 456,1050 1315,1050 1529,1264 1626,1264 1655.59,1234.41 Q3.4 ; Q3.7 Q3.4 ; U1.2 1998.31,1219.69 1988,1230 1940,1230 1914.13,1204.13 L1.1 1730.87,1204.13 C7.1 1728.39,1206.61 Q3.4
VBAT: J4.3 J5.3 J11.3 J13.3 J16.2 U1.18 U3.1 U3.2 U3.3 U3.4 U3.10 | length 7490.1
  Top Layer w10: U1.18 v2(2100,1300) ; U3.4 2401.32,1498.32 ; U3.3 2409.69,1518 ; U3.2 2409.69,1537.69 2410,1538 ; U3.1 2410,1557.37 U3.10
  Top Layer w20: J5.3 400,2250 1500,2250 J13.3 ; v1(2201,1385) 2342,1385 2409.69,1452.69 2409.69,1518 2409.69,1537.69 ; 2410,1538 2410,1557.37 2410,1587 2347,1650 1773,1650 1600,1823 J13.3 ; J11.3 3175,400 3175,1670 2965,1880 2790,1880 2735,1935 2735,2115 J16.2 2625,2075 2530,2075 2359,2246 1696,2246 J13.3
  Bottom Layer w20: J4.3 237,1937 237,2087 J5.3 ; v2(2100,1300) 2185,1385 v1(2201,1385)
VBATT_OK: Q2.1 U1.13 | length 116.5
  Top Layer w6: 2258,1178 2260.11,1175.89 Q2.1
  Top Layer w10: U1.13 2210,1200 2231.87,1178.13 2257.87,1178.13 ; 2258,1178 2257.87,1178.13 ; 2260.11,1178.13 2257.87,1178.13
VCC_MCU_RF: C3.1 J4.1 L2.1 U1.14 | length 4529.3
  Top Layer w10: J4.1 302,2050 452,1900 v1(880,1900) ; v1(1750,1900) 1950,1700 2890,1700 2970,1620 2970,1085 2935,1050 2750,1050 2725,1075 2725,1235 C3.1 ; U1.14 2272.99,1219.69 L2.1
  Top Layer w25: C3.1@2406.69,1231.69 C3.1
  Top Layer w40: L2.1 C3.1@2406.69,1231.69
  Bottom Layer w10: v1(880,1900) v1(1750,1900)
VCC_MCU_RF_EN/: J10.2 U1.6 | length 2011
  Top Layer w10: J10.2 1200,2072 1545,1727 1545,1415 v1(1380,1250) ; v1(1760,970) 1955,970 2060.63,1075.63 U1.6
  Bottom Layer w10: v1(1380,1250) 1660,970 v1(1760,970)
VCC_PULSESTRETCHER: J13.2 R3.2 | length 755.7
  Top Layer w10: R3.2 1637.91,1534.41 1642.5,1539 v1(1642.5,1680) ; v1(1700,1780) J13.2
  Bottom Layer w10: v1(1642.5,1680) 1700,1737.5 v1(1700,1780)
VGND_COMP: R14.1 R16.2 R25.2 U2.3 | length 364.7
  Top Layer w10: R25.2 R16.2 R14.1 1627.91,852.91 1656.37,881.37 1656.37,956.82 U2.3
VRDIV: R6.2 R8.2 R9.2 U1.8 | length 318
  Top Layer w10: U1.8 2100,1052.01 2096.5,1048.5 R8.2 R6.2 2173,984.5 2173,1041.5 R9.2
VSTOR: C4.1 C5.1 J10.3 J17.2 U1.19 | length 3664.2
  Top Layer w10: J17.2 425,1550 527,1448 1341,1448 1434,1541 1434,1721 1100,2055 J10.3 1171,2221 1423,2221 1558,2086 1558,1814 1779,1593 1952,1593 2060,1485 C5.1 2060,1353.5 C4.1 2068.5,1291.77 2078.5,1281.77 2078.5,1281.5 2080.31,1279.69 U1.19
VTEG_COMP: R4.1 R5.2 R10.1 U2.1 | length 277.7
  Top Layer w10: R10.1 R4.1 ; R5.2 R4.1 ; U2.1 1604.41,934.41 1595,925 1542.91,925 R4.1
WAKEUP: J3.4 U3.8 | length 442.4
  Top Layer w10: U3.8 2595,1518 2626,1549 2851,1549 J3.4
pads on no net: FID1.1 FID2.1 FID3.1 J2.3 J2.5 J2.6 J2.7 J2.8 J2.10 J2.11 J2.12 J2.13 J2.14 J2.16 J2.18 J2.20 J3.1 J3.3 J3.5 J3.7 J3.8 J3.9 J3.10 J3.11 J3.13 J3.14 J3.15 J3.17 J3.19 J5.1 Logo1.0 SH-J1.0 SH-J2.0 SH-J3.0 SH-J4.0 SH-J5.0 SH-J6.0 SH-J7.0 SH-J8.0 SH-J9.0 SH-J10.0 SH-J11.0 U3.9 U5.22 U5.25
copper on no net:
  other v3: 750,626.61 711.61,665 750,665 788.39,665 750,703.39

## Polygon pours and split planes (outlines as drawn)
GND on Bottom Layer "Bottom Layer-No Net 1" (solid, remove dead copper, pour order 3): 770,530 680,530 610,600 605,605 605,825 635,855 670,890 710,890 830,890 850,870 885,835 885,715 885,600 815,530 810,530
GND_EH on Bottom Layer "Bottom Layer-No Net" (solid, remove dead copper, pour order 2): 30,2296.09 30,-3.91 4030,-3.91 4030,2296.09 30,2296.09

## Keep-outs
Keep-Out Layer:
  lines w15: -7.5,0 ccw(c0,0) 0,-7.5 ; -7.5,0 ccw(c0,0) 0,-7.5 ; -7.5,0 -7.5,2300 ; -7.5,2300 cw(c0,2300) 0,2307.5 ; -7.5,2300 cw(c0,2300) 0,2307.5 ; 0,-7.5 4000,-7.5 ; 0,2307.5 4000,2307.5 ; 4000,-7.5 ccw(c4000,0) 4007.5,0 ; 4000,-7.5 ccw(c4000,0) 4007.5,0 ; 4000,2307.5 cw(c4000,2300) 4007.5,2300 ; 4000,2307.5 cw(c4000,2300) 4007.5,2300 ; 4007.5,0 4007.5,2300
  text ".Layer_Name" at 577,-858.49 h60

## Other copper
Top Layer:
  text "©" at 1020,220 h105
  text ".CopyrightYear" at 1140,220 h60
  text "TI" at 1416,220 h60
  text ".Layer_Name" at 577,-858.49 h60
Bottom Layer:
  text ".Layer_Name" at 577,-858.49 h60

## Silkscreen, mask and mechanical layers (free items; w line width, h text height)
Top Overlay:
  text ".PRJ_Number" at 1620,425 h60
  text ".PCB_Rev" at 2220,425 h60
  text ".Layer_Name" at 577,-858.49 h60
Bottom Overlay:
  text ".Layer_Name" at 577,-858.49 h60
Top Paste:
  text ".Layer_Name" at 577,-858.49 h60
Bottom Paste:
  text ".Layer_Name" at 577,-858.49 h60
Top Solder:
  text ".Layer_Name" at 577,-858.49 h60
  text ".Layer_Name" at 577,-858.49 h60
Bottom Solder:
  text ".Layer_Name" at 577,-858.49 h60
Drill Guide:
  text ".Layer_Name" at 577,-858.49 h60
M1 Board Outline:
  the board outline again, w10
  text ".Layer_Name" at 577,-858.49 h60
M2 Board Dimensions:
  rectangle: 125,-400 500,-275
  rectangle: 0,-275 125,-150
  lines w7: 0,-275 1000,-275 ; 125,-400 125,-150 ; 250,-400 250,-150 ; 500,-400 500,-150 ; 750,-400 750,-150 ; 0,-400 0,-150 1000,-150 1000,-400 0,-400
  text ".Layer_Name" at 577,-858.49 h60
M3 3D STEP Top:
  text ".Layer_Name" at 577,-858.49 h60
M4 3D STEP Bottom:
  text ".Layer_Name" at 577,-858.49 h60
M5 Assembly Top:
  lines w10: -292,-930.17 6308,-930.17 ; -292,-726.83 6310,-726.83 ; -292,-523.5 -292,-1133.5 3713,-1133.5 6310,-1133.5 6310,-523.5 -291.5,-523.5 -291.5,-1133.5 1284,-1133.5 ; 2173,-1133.5 2173,-523.5 ; 3440,-726.83 3440,-523.5 ; 4280,-726.83 4280,-523.5 ; 4902,-1140 4902,-937.17
  text "COMPONENTS MARKED 'DNP' SHOULD NOT BE POPULATED." at 1153.5,-318.5 h60
  text "ASSEMBLY VARIANT:" at 1153,-434 h60
  text ".VariantName" at 2189,-434 h60
  text "PCB VIEWED FROM TOP SIDE" at -228.5,-655.67 h60
  text "BOARD #:" at 2248,-655.67 h60
  text ".PRJ_Number" at 2793.5,-655.67 h60
  text "REV:" at 3638,-655.67 h60
  text ".PCB_Rev" at 3929.5,-655.67 h60
  text "SVN REV:" at 4476,-655.67 h60
  text ".VersionControl_RevNumber" at 4982,-655.67 h60
  text "PLOT NAME =" at -228.5,-1064.34 h60
  text ".plot_File_Name" at 577,-1064.34 h60
  text "GENERATED    :" at 2250,-1064.34 h60
  text ".Print_Date" at 3119.5,-1064.34 h60
  text ".Print_Time" at 3848.5,-1064.34 h60
  text "TEXAS INSTRUMENTS" at 5113,-1064.34 h60
M6 Assembly Bottom:
  lines w10: -292.5,-727.33 6309.5,-727.33 ; -290.5,-930.67 6309.5,-930.67 ; 1115.5,-1140.5 1115.5,-937.67 ; 1737.5,-727.33 1737.5,-524 ; 2577.5,-727.33 2577.5,-524 ; 3844.5,-1134 3844.5,-524 ; 4733.5,-1134 6309,-1134 6309,-524 -292.5,-524 -292.5,-1134 2304.5,-1134 6309.5,-1134 6309.5,-524
  text "COMPONENTS MARKED 'DNP' SHOULD NOT BE POPULATED." at 6102,-318 h60
  text ".VariantName" at 5058,-434 h60
  text "ASSEMBLY VARIANT:" at 6097,-434 h60
  text ".VersionControl_RevNumber" at 1035.5,-656.17 h60
  text "SVN REV:" at 1541.5,-656.17 h60
  text ".PCB_Rev" at 2088,-656.17 h60
  text "REV:" at 2379.5,-656.17 h60
  text ".PRJ_Number" at 3224,-656.17 h60
  text "BOARD #:" at 3769.5,-656.17 h60
  text "PCB VIEWED FROM BOTTOM SIDE" at 6246,-656.17 h60
  text "TEXAS INSTRUMENTS" at 904.5,-1064.84 h60
  text ".Print_Time" at 2169,-1064.84 h60
  text ".Print_Date" at 2898,-1064.84 h60
  text "GENERATED    :" at 3767.5,-1064.84 h60
  text ".plot_File_Name" at 5440.5,-1064.84 h60
  text "PLOT NAME =" at 6246,-1064.84 h60
M9 Title Sheet:
  drawing of 57 lines, arcs and shapes, not listed
  text "1" at 739.84,8036.5 h70
  text "2" at 3235.5,8036.5 h70
  text "3" at 5724.84,8036.5 h70
  text "4" at 8231.51,8036.5 h70
  text "5" at 10730.5,8036.5 h70
  text "6" at 13235.5,8036.5 h70
  text "A" at -416.5,6893.5 h70
  text "A" at 14383.5,6893.5 h70
  text "B" at -416.5,4513.5 h70
  text "B" at 14383.5,4513.5 h70
  text "C" at -416.5,2138.5 h70
  text "C" at 14383.5,2138.5 h70
  text "PROJECT TITLE:" at 11343.5,277.5 h45
  text ".PRJ_Title" at 11393.5,144.17 h70
  text "DESIGNED FOR:" at 11343.5,-23.5 h45
  text ".PRJ_Customer" at 11393.5,-163.5 h70
  text "D" at -416.5,-231.5 h70
  text "D" at 14383.5,-231.5 h70
  text "FILE NAME:" at 11343.5,-323.5 h45
  text ".PCB_File_Name_No_Path" at 11393.5,-443.5 h70
  text "Texas Instruments (TI) and/or its licensors do not warrant the accuracy or completeness of this specification" at 6374,-605.34 h45
  text "ENGINEER:" at 11343.5,-613.5 h45
  text "LAYOUT BY:" at 12848.5,-613.5 h45
  text "or any information contained therein. TI and/or its licensors do not warrant that this design will meet" at 6329.01,-718 h45
  text ".PRJ_Engineer" at 11393.5,-768.49 h70
  text ".PCB_Layout" at 12899,-768.49 h70
  text "the specifications, will be suitable for your application or fit for any particular purpose, or will operate in" at 6329.01,-830.67 h45
  text ".Layer_Name" at 577,-858.49 h60
  text "ALTIUM DESIGNER VERSION:" at 12848.5,-923.5 h45
  text "an implementation. TI and/or its licensors do not warrant that the design is production worthy. You should" at 6329.01,-943.33 h45
  text "completely validate and test your design implementation to confirm the system functionality for your application." at 6374,-1056 h45
  text ".print_Scale" at 11393.5,-1056.83 h70
  text ".Application_BuildNumber" at 12899,-1056.83 h70
  text "1" at 739.84,-1263.5 h70
  text "2" at 3235.5,-1263.5 h70
  text "3" at 5724.84,-1263.5 h70
  text "4" at 8231.51,-1263.5 h70
  text "5" at 10730.5,-1263.5 h70
  text "6" at 13235.5,-1263.5 h70
M10 Fab Notes:
  drawing of 185 lines, arcs and shapes, not listed
  text "DESIGN INFORMATION" at 12381.02,5910 h60
  text "MIN. TRACK WIDTH:" at 11736.46,5730 h60
  text "6" at 12832.7,5730 h60
  text "MIL" at 12987.46,5730 h60
  text "MIN. CLEARANCE:" at 11736.46,5598 h60
  text "0.2" at 12772.7,5598 h60
  text "mm" at 12987.46,5598 h60
  text "MIN. VIA PAD SIZE:" at 11736.46,5466 h60
  text "20" at 12802.71,5466 h60
  text "MIL" at 12987.46,5466 h60
  text "0.05mm (2MIL)" at 12431.46,5324.29 h60
  text "MINIMUM ANNULAR RING" at 11407.23,5320 h60
  text "EXTERNAL" at 13139.46,5320 h60
  text "PER" at 11607.23,5202 h60
  text "IPC-D-275 CLASS 2 LEVEL C" at 11827.23,5202 h60
  text "MIL, HOLES" at 13315.46,5089.71 h60
  text "+/-" at 12923,5089 h60
  text "+/-" at 13777,5089 h60
  text "REGISTRATION TOLERANCES:" at 11407.23,5084 h60
  text "METAL" at 12607,5084 h60
  text "5" at 13183.2,5084 h60
  text "3" at 14016.2,5084 h60
  text "MIL" at 14132.46,5084 h60
  text "MATERIAL:" at 11332.46,4874.54 h60
  text "FR-4 High Tg" at 12318.9,4734.21 h60
  text "FR-408" at 11753.46,4725.64 h60
  text "X" at 12165.46,4725.64 h60
  text "OTHER" at 13241.46,4725.64 h60
  text "62 MIL (1.6mm) +/-10%" at 12073.56,4562.92 h60
  text "THICKNESS:" at 11407.23,4558.64 h60
  text "X" at 11945.4,4558.64 h60
  text "OTHER" at 13358.46,4558.64 h60
  text "TOLERANCE:" at 11407.23,4400.64 h60
  text "X" at 12246.53,4400.64 h60
  text "ANSI IPC-6012 TYPE 3 CLASS 2" at 12433.48,4400.64 h60
  text "OTHER +/-" at 12433.46,4244.64 h60
  text "BOW & TWIST:" at 11407.23,4087.64 h60
  text "X" at 12246.53,4087.64 h60
  text "ANSI IPC-6012 TYPE 3 CLASS 2" at 12433.48,4087.64 h60
  text "OTHER +/-" at 12433.46,3929.13 h60
  text "DRILLING:" at 11332.46,3790.64 h60
  text "REFERENCE:" at 11407.23,3673.64 h60
  text "X" at 12055.46,3673.64 h60
  text "AS SHOWN" at 12242.46,3673.64 h60
  text "X" at 12956.46,3673.64 h60
  text "NC_DRILL FILES" at 13093.46,3673.64 h60
  text "PTH MIN COPPER THICKNESS:" at 11407.23,3515.64 h60
  text "X" at 12757.46,3515.64 h60
  text "1MIL" at 12894.46,3515.64 h60
  text "OTHER" at 13391.46,3515.64 h60
  text "BOARD FINISH:" at 11332.46,3356.64 h60
  text "SILKSCREEN:" at 11487.68,3238.64 h60
  text "X" at 12436.46,3238.64 h60
  text "TOP" at 12562.46,3238.64 h60
  text "X" at 12946.46,3238.64 h60
  text "BOTTOM" at 13073.46,3238.64 h60
  text "SILKSCREEN COLOR:" at 11487.68,3071.64 h60
  text "X" at 12435.42,3071.64 h60
  text "WHITE" at 12562.46,3071.64 h60
  text "OTHER" at 13073.46,3071.64 h60
  text "SOLDER RESIST COLOR:" at 11487.68,2901.64 h60
  text "X" at 12055.42,2742.44 h60
  text "GREEN" at 12182.46,2742.44 h60
  text "BLUE" at 12773.46,2742.44 h60
  text "OTHER" at 13311.46,2742.44 h60
  text "IMMERSION GOLD (ENIG)" at 12393.46,2553.92 h60
  text "ENEPIG" at 13731,2550.64 h60
  text "SURFACE FINISH:" at 11332.46,2549.64 h60
  text "X" at 12206.51,2549.64 h60
  text "IMM. TIN/SILVER OR EQUIV" at 11662,2392.64 h60
  text "OTHER" at 13093.46,2392.64 h60
  text "ARRAY/PANEL:" at 11332.46,2213.64 h60
  text "CUT AND TRIM PER MECH LAYER 1" at 12393.46,2209.35 h60
  text "N.C. ROUTE" at 12393.46,2057.64 h60
  text "X" at 13072.46,2057.64 h60
  text "V. SCORE" at 13259.46,2057.64 h60
  text "CERTIFICATION:" at 11332.46,1920.64 h60
  text "MATERIALS AND WORKMANSHIP FOR ALL PCBS" at 12057.46,1920.64 h60
  text "TO MEET OR EXCEED THE REQUIREMENTS OF:" at 12057.46,1822.64 h60
  text "X" at 11683.96,1686.13 h60
  text "ANSI IPC-A-600F CLASS ->" at 11822.96,1686.13 h60
  text "X" at 13462.02,1686.13 h60
  text "2" at 13580.96,1686.14 h60
  text "1" at 13265.96,1684.64 h60
  text "3" at 13934.96,1684.64 h60
  text "X" at 11686.02,1526.64 h60
  text "UL 94V-0" at 11822.96,1526.64 h60
  text "X" at 12498.02,1526.64 h60
  text "RoHS" at 12634.96,1526.64 h60
  text "OTHER" at 13279.36,1526.64 h60
  text "PER ORDER" at 13676.42,1526.64 h60
  text "ADDITIONAL REQUIREMENTS:" at 11332.46,1385.64 h60
  text "MICROSECTION:" at 11407.23,1270.64 h60
  text "YES" at 12312.96,1270.64 h60
  text "REQUIRED" at 13174.46,1114.49 h60
  text "BARE BOARD ELEC. TEST:" at 11407.23,1111.64 h60
  text "NONE" at 12712.96,1111.64 h60
  text "X" at 13047.46,1111.64 h60
  text "PER ORDER" at 13766.46,1111.64 h60
  text "MANUFACTURER'S UL:" at 11407.23,954.64 h60
  text "RAIL" at 12572.96,950.35 h60
  text "METAL" at 13064.77,950.35 h60
  text "X" at 13440,950 h60
  text "SILK" at 13576.46,950.35 h60
  text ".Layer_Name" at 577,-858.49 h60
M11 Gerber Information:
  lines w10: -292,-930.17 6308,-930.17 ; -292,-726.83 6310,-726.83 ; -292,-523.5 -292,-1133.5 3713,-1133.5 6310,-1133.5 6310,-523.5 -291.5,-523.5 -291.5,-1133.5 1284,-1133.5 ; 2173,-1133.5 2173,-523.5 ; 3440,-726.83 3440,-523.5 ; 4280,-726.83 4280,-523.5 ; 4902,-1140 4902,-937.17
  text "ALL ARTWORK VIEWED FROM TOP SIDE" at -228.5,-655.67 h60
  text "BOARD #:" at 2248,-655.67 h60
  text ".PRJ_Number" at 2793.5,-655.67 h60
  text "REV:" at 3638,-655.67 h60
  text ".PCB_Rev" at 3929.5,-655.67 h60
  text "SVN REV:" at 4476,-655.67 h60
  text ".VersionControl_RevNumber" at 4982,-655.67 h60
  text "LAYER NAME =" at -228.5,-858.49 h60
  text "PLOT NAME =" at -228.5,-1064.34 h60
  text ".plot_File_Name" at 577,-1064.34 h60
  text "GENERATED    :" at 2250,-1064.34 h60
  text ".Print_Date" at 3119.5,-1064.34 h60
  text ".Print_Time" at 3848.5,-1064.34 h60
  text "TEXAS INSTRUMENTS" at 5113,-1064.34 h60
M12 Stackup:
  drawing of 191 lines, arcs and shapes, not listed
  text "Layer" at 9790.58,7830 h60
  text "Name" at 10200.49,7830 h60
  text "Material" at 11130.23,7830 h60
  text "Thickness" at 11990,7830 h60
  text "Constant" at 12639.84,7830 h60
  text "Board Layer Stack" at 13209.7,7830 h60
  text "1" at 9790.58,7710 h60
  text "Top Overlay" at 10200.49,7710 h60
  text "2" at 9790.58,7590 h60
  text "Top Solder" at 10200.49,7590 h60
  text "Solder Resist" at 11130.23,7590 h60
  text "0.40mil" at 11990,7590 h60
  text "3.5" at 12639.84,7590 h60
  text "3" at 9790.58,7470 h60
  text "Top Layer" at 10200.49,7470 h60
  text "Copper" at 11130.23,7470 h60
  text "1.40mil" at 11990,7470 h60
  text "4" at 9790.58,7350 h60
  text "Dielectric1" at 10200.49,7350 h60
  text "FR-4" at 11130.23,7350 h60
  text "59.20mil" at 11990,7350 h60
  text "4.8" at 12639.84,7350 h60
  text "5" at 9790.58,7230 h60
  text "Bottom Layer" at 10200.49,7230 h60
  text "Copper" at 11130.23,7230 h60
  text "1.40mil" at 11990,7230 h60
  text "6" at 9790.58,7110 h60
  text "Bottom Solder" at 10200.49,7110 h60
  text "Solder Resist" at 11130.23,7110 h60
  text "0.40mil" at 11990,7110 h60
  text "3.5" at 12639.84,7110 h60
  text "7" at 9790.58,6990 h60
  text "Bottom Overlay" at 10200.49,6990 h60
  text ".Layer_Name" at 577,-858.49 h60
M13 Component Bodies Top:
  text ".Layer_Name" at 577,-858.49 h60
M14 Component Bodies Bottom:
  text ".Layer_Name" at 577,-858.49 h60
M15 Courtyards Top:
  text ".Layer_Name" at 577,-858.49 h60
M16 Courtyards Bottom:
  text ".Layer_Name" at 577,-858.49 h60
Drill Drawing:
  circle w1: c5892.72,3121.72 r24.89
  lines w1: 5867.83,2648.88 5892.72,2661.32 5917.6,2648.88 5905.16,2673.76 5917.6,2698.65 5892.72,2686.21 5867.83,2698.65 5880.27,2673.76 5867.83,2648.88 ; 5867.83,2810.64 5880.27,2810.64 5892.72,2798.2 5905.16,2810.64 5917.6,2810.64 5905.16,2823.08 5917.6,2835.53 5905.16,2835.53 5892.72,2847.97 5880.27,2835.53 5867.83,2835.53 5880.27,2823.08 5867.83,2810.64 ; 5867.83,2997.29 5917.6,2997.29 5892.72,2947.52 5867.83,2997.29 ; 5867.83,3246.16 5917.6,3246.16 5917.6,3295.93 5867.83,3295.93 5867.83,3246.16
  lines w12: 5800,2604.08 7918.02,2604.08 ; 5800,3350.68 7918.02,3350.68 ; 6170.36,2454.76 6170.36,3500 ; 6527.36,2454.76 6527.36,3500 ; 7188.93,2454.76 7188.93,3500 ; 7473.07,2454.76 7473.07,3500 ; 5800,2454.76 7918.02,2454.76 7918.02,3500 5800,3500 5800,2454.76
  text "Symbol" at 5889.59,3395.48 h72
  text "Quantity" at 6215.16,3395.48 h72
  text "Finished Hole Size" at 6572.16,3395.48 h72
  text "Plated" at 7233.72,3395.48 h72
  text "Hole Type" at 7517.86,3395.48 h72
  text "9" at 6215.16,3246.16 h60
  text "7.87mil (0.200mm)" at 6572.16,3246.16 h60
  text "PTH" at 7233.72,3246.16 h60
  text "Round" at 7517.86,3246.16 h60
  text "15" at 6215.16,3096.84 h60
  text "12.00mil (0.305mm)" at 6572.16,3096.84 h60
  text "PTH" at 7233.72,3096.84 h60
  text "Round" at 7517.86,3096.84 h60
  text "30" at 6215.16,2947.52 h60
  text "16.00mil (0.406mm)" at 6572.16,2947.52 h60
  text "PTH" at 7233.72,2947.52 h60
  text "Round" at 7517.86,2947.52 h60
  text "3" at 6215.16,2798.2 h60
  text "39.37mil (1.000mm)" at 6572.16,2798.2 h60
  text "PTH" at 7233.72,2798.2 h60
  text "Round" at 7517.86,2798.2 h60
  text "81" at 6215.16,2648.88 h60
  text "45.28mil (1.150mm)" at 6572.16,2648.88 h60
  text "PTH" at 7233.72,2648.88 h60
  text "Round" at 7517.86,2648.88 h60
  text "138 Total" at 6215.16,2499.56 h60
  text ".Layer_Name" at 577,-858.49 h60
M17 DELETED TEXT:
  text "UL94V-0" at 1350,2600 h60
  text ".VersionControl_RevNumber" at 2821,2579.5 h60
  text "SVN:" at 3100,2579.5 h60
  text "MADE IN U.S." at 3100,2460 h60

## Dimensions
0,0 to 4000,0 on M2 Board Dimensions
0,-400 to 1000,-400 on M2 Board Dimensions
0,0 to 0,2300 on M2 Board Dimensions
